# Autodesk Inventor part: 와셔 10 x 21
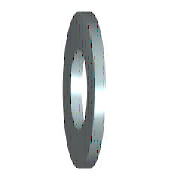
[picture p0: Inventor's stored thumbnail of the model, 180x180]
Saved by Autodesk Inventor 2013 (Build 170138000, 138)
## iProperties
Created: 2012-02
Part Number: 와셔 10 x 21
Material: 강철, 연강
Description: 평면 와셔
Document SubType Name: Modeling
Standard: KS B 1326
Designer: mduedu
Standards Organization: KS
Language: ko-KR
Size Designation: 10x21
Categories: <MemberInstance><Categories><Category DisplayName="조임쇠" InternalName="e4da775c-781d-43d5-af7c-5136215cf5a6" Mnemonic="FSTN"><Category DisplayName="와셔" InternalN
Density: 1 g/cm^3
IsCustomPart: 1
Author: mduedu
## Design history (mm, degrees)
sketch "스케치"
  geometry: C1 r 10.5 at (0, 0); C2 r 5.25 at (0, 0); 1 further point
  constraints: 2 centre point, 2 coincident
  dimensions: "d0" = 10.5 diameter of C2 (= SD1); "d1" = 21 diameter of C1 (= SD2)
extrude "본체" new body sketch "스케치" distance "d2" = 2 (= SD); taper "d3" = 0 deg
workaxis "Work Axis1"
workplane "Work Plane1"
body "Solid1"
other parameters: "SD1" = 10.5 [user parameter; used in 1 equation term], "SD2" = 21 [user parameter; used in 1 equation term], "SD" = 2 [user parameter; used in 1 equation term], "d4" = 0, "d5" = 0, "d6" = 0, "d7" = 0
